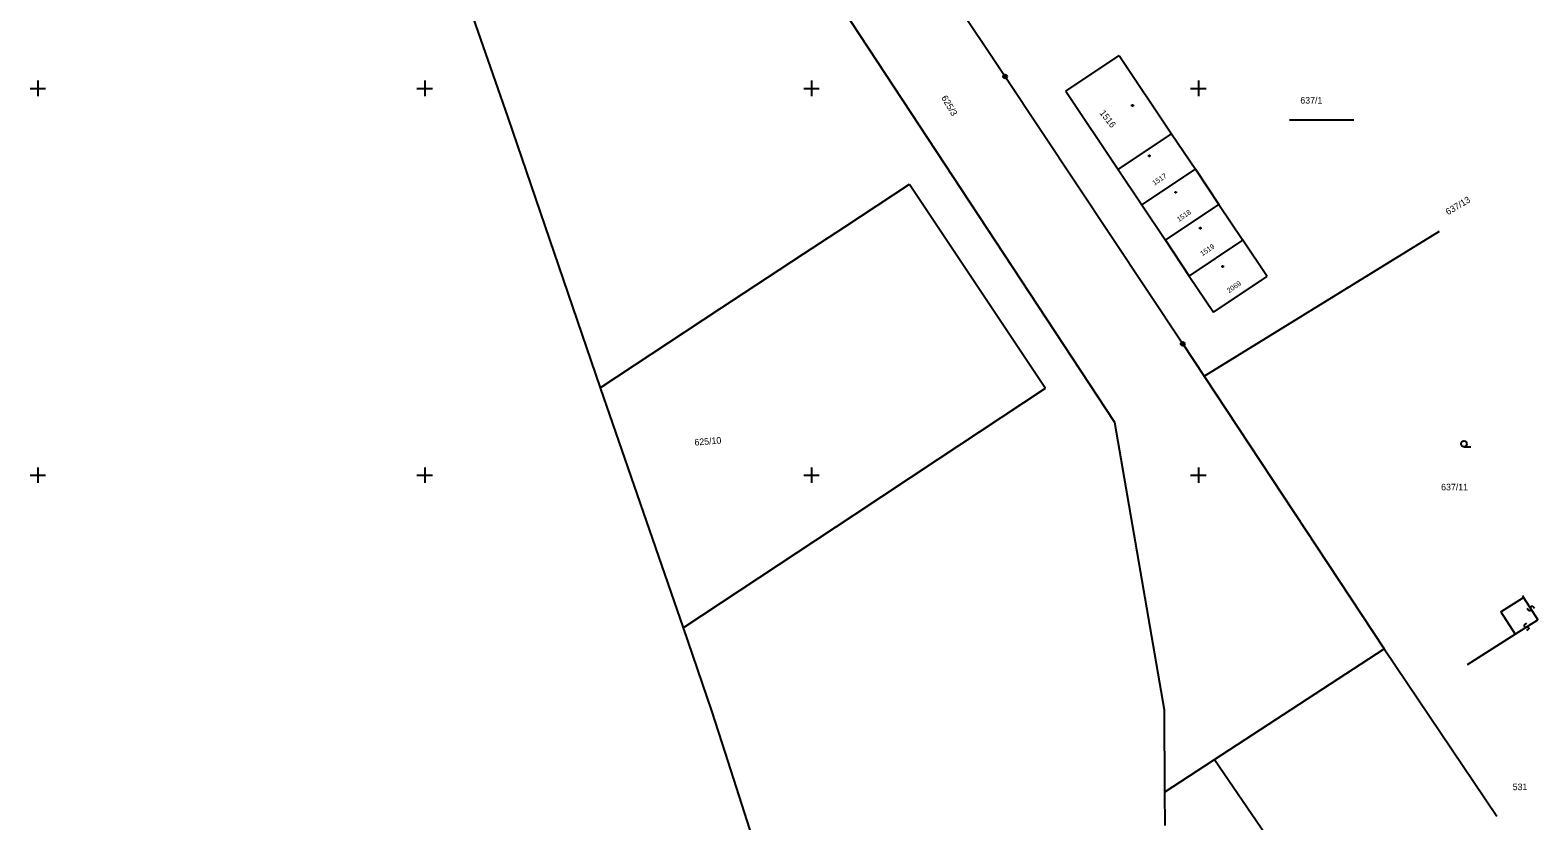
# Model space of a CAD drawing. Extents: x -493352 to -492964, y -1127001 to -1126712.
# Drawn here: x -493080.6 to -492963.7, y -1126856.8 to -1126795.5 of the extents above; entities that cross this region are included whole.
import ezdxf

# ---------------------------------------------------------------- set-up
doc = ezdxf.new("R2010")
doc.units = 0
doc.layers.add('katastrální mapa', color=7, linetype='Continuous')
doc.layers.add('síť', color=7, linetype='Continuous')

msp = doc.modelspace()

# ---------------------------------------------------------------- linework, layer by layer
at = {"layer": 'katastrální mapa'}
for p, q in [((-493050.98, -1126780.92), (-493043.56, -1126802.27)), ((-493023.73, -1126784.49), (-492996.49, -1126825.9)), ((-493009.83, -1126791.82), (-493004.99, -1126799.08)), ((-493000.29, -1126800.23), (-492996.13, -1126797.45)), ((-492996.13, -1126797.45), (-492992.07, -1126803.52)), ((-493004.99, -1126799.08), (-492991.21, -1126819.81)), ((-493000.29, -1126800.23), (-492996.22, -1126806.3)), ((-492995.15, -1126801.28), (-492995.06, -1126801.28)), ((-492995.15, -1126801.37), (-492995.15, -1126801.28)), ((-492995.06, -1126801.37), (-492995.15, -1126801.37)), ((-492995.06, -1126801.28), (-492995.06, -1126801.37)), ((-493043.56, -1126802.27), (-493036.4, -1126823.23)), ((-492977.94, -1126802.46), (-492982.94, -1126802.46)), ((-492996.22, -1126806.3), (-492992.07, -1126803.52)), ((-492992.07, -1126803.52), (-492990.23, -1126806.26)), ((-492993.85, -1126805.19), (-492993.76, -1126805.19)), ((-492993.85, -1126805.28), (-492993.85, -1126805.19)), ((-492993.76, -1126805.28), (-492993.85, -1126805.28)), ((-492993.76, -1126805.19), (-492993.76, -1126805.28)), ((-492996.22, -1126806.3), (-492994.39, -1126809.04)), ((-492994.39, -1126809.04), (-492990.23, -1126806.26)), ((-492990.23, -1126806.26), (-492988.4, -1126809)), ((-493017.42, -1126810.73), (-493012.4, -1126807.43)), ((-493012.4, -1126807.43), (-493001.85, -1126823.25)), ((-492991.81, -1126808.02), (-492991.72, -1126808.02)), ((-492991.81, -1126808.11), (-492991.81, -1126808.02)), ((-492991.72, -1126808.11), (-492991.81, -1126808.11)), ((-492991.72, -1126808.02), (-492991.72, -1126808.11)), ((-492994.39, -1126809.04), (-492992.55, -1126811.78)), ((-492992.55, -1126811.78), (-492988.4, -1126809)), ((-492988.4, -1126809), (-492986.54, -1126811.78)), ((-493020.61, -1126812.84), (-493017.42, -1126810.73)), ((-492989.89, -1126810.8), (-492989.8, -1126810.8)), ((-492989.89, -1126810.89), (-492989.89, -1126810.8)), ((-492989.8, -1126810.89), (-492989.89, -1126810.89)), ((-492989.8, -1126810.8), (-492989.8, -1126810.89)), ((-492989.55, -1126822.31), (-492971.3, -1126811.07)), ((-492992.55, -1126811.78), (-492990.7, -1126814.56)), ((-492990.7, -1126814.56), (-492986.54, -1126811.78)), ((-492984.66, -1126814.58), (-492986.54, -1126811.78)), ((-493027.11, -1126817.11), (-493020.61, -1126812.84)), ((-492990.7, -1126814.56), (-492988.83, -1126817.36)), ((-492988.83, -1126817.36), (-492984.66, -1126814.58)), ((-492988.16, -1126813.77), (-492988.07, -1126813.77)), ((-492988.16, -1126813.86), (-492988.16, -1126813.77)), ((-492988.07, -1126813.86), (-492988.16, -1126813.86)), ((-492988.07, -1126813.77), (-492988.07, -1126813.86)), ((-493036.4, -1126823.23), (-493027.11, -1126817.11)), ((-492991.21, -1126819.81), (-492989.55, -1126822.31)), ((-492989.55, -1126822.31), (-492975.58, -1126843.46)), ((-493036.4, -1126823.23), (-493029.96, -1126841.85)), ((-493006.97, -1126826.64), (-493001.85, -1126823.25)), ((-492996.49, -1126825.9), (-492992.64, -1126848.19)), ((-493010.19, -1126828.77), (-493006.97, -1126826.64)), ((-492969.4, -1126827.8), (-492968.87, -1126827.8)), ((-493016.7, -1126833.08), (-493010.19, -1126828.77)), ((-493029.96, -1126841.85), (-493016.7, -1126833.08)), ((-492966.54, -1126840.61), (-492964.77, -1126839.48)), ((-492964.85, -1126839.34), (-492964.77, -1126839.48)), ((-492964.77, -1126839.48), (-492963.67, -1126841.21)), ((-492964.37, -1126840.51), (-492964.5, -1126840.35)), ((-492964.21, -1126840.2), (-492964.23, -1126840.28)), ((-492964.23, -1126840.28), (-492964.21, -1126840.41)), ((-492964.16, -1126840.16), (-492964.21, -1126840.2)), ((-492964.07, -1126840.18), (-492964.16, -1126840.16)), ((-492963.94, -1126840.34), (-492964.07, -1126840.18)), ((-492966.54, -1126840.61), (-492965.44, -1126842.33)), ((-492965.44, -1126842.33), (-492963.67, -1126841.21)), ((-492964.56, -1126841.49), (-492964.72, -1126841.62)), ((-492964.28, -1126840.53), (-492964.37, -1126840.51)), ((-492964.23, -1126840.49), (-492964.28, -1126840.53)), ((-492964.21, -1126840.41), (-492964.23, -1126840.49)), ((-493029.96, -1126841.85), (-493027.76, -1126848.29)), ((-492969.13, -1126844.68), (-492965.44, -1126842.33)), ((-492964.72, -1126841.62), (-492964.74, -1126841.71)), ((-492964.74, -1126841.71), (-492964.7, -1126841.76)), ((-492964.7, -1126841.76), (-492964.62, -1126841.78)), ((-492964.62, -1126841.78), (-492964.49, -1126841.76)), ((-492964.39, -1126841.92), (-492964.55, -1126842.05)), ((-492964.49, -1126841.76), (-492964.41, -1126841.78)), ((-492964.41, -1126841.78), (-492964.37, -1126841.83)), ((-492964.37, -1126841.83), (-492964.39, -1126841.92)), ((-492988.76, -1126852.06), (-492975.58, -1126843.46)), ((-492975.58, -1126843.46), (-492966.85, -1126856.45)), ((-493027.76, -1126848.29), (-493026.71, -1126851.57)), ((-492992.64, -1126848.19), (-492992.62, -1126854.58)), ((-493026.71, -1126851.57), (-493022.46, -1126864.72)), ((-492992.62, -1126854.58), (-492988.76, -1126852.06)), ((-492988.76, -1126852.06), (-492983.15, -1126860.22)), ((-492992.62, -1126854.58), (-492992.61, -1126857.17))]:
    msp.add_line(p, q, dxfattribs=at)
for centre, radius in [((-493004.99, -1126799.08), 0.15), ((-493004.99, -1126799.08), 0.003), ((-492991.21, -1126819.81), 0.15), ((-492991.21, -1126819.81), 0.003), ((-492969.4, -1126827.57), 0.225)]:
    msp.add_circle(centre, radius, dxfattribs=at)
at = {"layer": 'síť'}
for p, q in [((-493080, -1126799.4), (-493080, -1126800.6)), ((-493050, -1126799.4), (-493050, -1126800.6)), ((-493020, -1126799.4), (-493020, -1126800.6)), ((-492990, -1126799.4), (-492990, -1126800.6)), ((-493080.6, -1126800), (-493079.4, -1126800)), ((-493050.6, -1126800), (-493049.4, -1126800)), ((-493020.6, -1126800), (-493019.4, -1126800)), ((-492990.6, -1126800), (-492989.4, -1126800)), ((-493080, -1126829.4), (-493080, -1126830.6)), ((-493050, -1126829.4), (-493050, -1126830.6)), ((-493020, -1126829.4), (-493020, -1126830.6)), ((-492990, -1126829.4), (-492990, -1126830.6)), ((-493080.6, -1126830), (-493079.4, -1126830)), ((-493050.6, -1126830), (-493049.4, -1126830)), ((-493020.6, -1126830), (-493019.4, -1126830)), ((-492990.6, -1126830), (-492989.4, -1126830))]:
    msp.add_line(p, q, dxfattribs=at)

# ---------------------------------------------------------------- texts
at = {"layer": 'katastrální mapa'}
for s, height, rotation, p in [('625/3', 0.51, 300.519, (-493009.96, -1126800.73)), ('1516', 0.51, 308.133, (-492997.69, -1126801.92)), ('1517', 0.39, 34.209, (-492993.4, -1126807.55)), ('637/13', 0.51, 30.771, (-492970.64, -1126809.85)), ('1518', 0.39, 34.209, (-492991.51, -1126810.37)), ('1519', 0.39, 34.209, (-492989.69, -1126813.03)), ('2069', 0.39, 34.2, (-492987.63, -1126815.9)), ('625/10', 0.51, 4.644, (-493029.06, -1126827.71))]:
    msp.add_text(s, height=height, rotation=rotation, dxfattribs=at).set_placement(p)
for s, p in [('637/1', (-492982.09, -1126801.18)), ('637/11', (-492971.17, -1126831.18)), ('531', (-492965.62, -1126854.43))]:
    msp.add_text(s, height=0.51, dxfattribs=at).set_placement(p)

doc.saveas('drawing.dxf')
